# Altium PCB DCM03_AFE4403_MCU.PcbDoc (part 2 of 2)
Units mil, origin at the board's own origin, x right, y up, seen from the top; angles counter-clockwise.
Board outline 608.6 x 413.33 mil, 6 copper layers (Top Layer, Mid-Layer 1, Mid-Layer 2, Mid-Layer 3, Mid-Layer 4, Bottom Layer); 22 components, 39 nets, 207 pads, 99 vias.
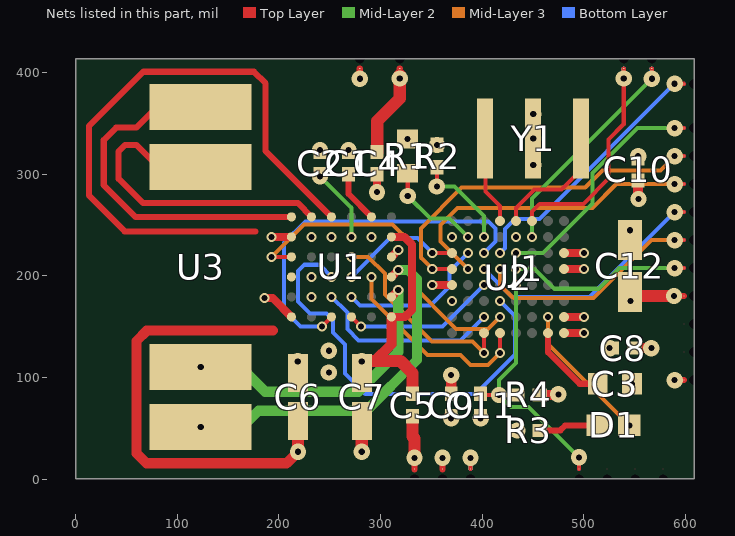
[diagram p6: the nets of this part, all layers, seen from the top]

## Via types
v1: diameter 16, hole 6, Top Layer to Bottom Layer, 50 vias
v2: diameter 10, hole 6, Top Layer to Bottom Layer, 49 vias

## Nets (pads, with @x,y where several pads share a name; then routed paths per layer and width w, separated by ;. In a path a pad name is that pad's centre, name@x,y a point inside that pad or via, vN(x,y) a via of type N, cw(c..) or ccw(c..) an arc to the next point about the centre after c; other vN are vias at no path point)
AFE_ADC_RDY: U1.D5 U2.F7 | length 187.1
  Bottom Layer w4: v2(251.76,179.42) 267.35,163.83 267.35,147.62 278.49,136.48 378.88,136.48 v2(401.98,159.58)
AFE_DIAG_END: U1.B4 U2.E8 | length 199.8
  Top Layer w4: v2(417.73,124.33) U2.E8@417.73,143.83
  Mid-Layer 3 w4: v2(291.13,199.1) 291.13,177.29 346.41,122.01 378.87,122.01 388.57,112.31 405.71,112.31 v2(417.73,124.33)
AFE_PDNZ: U1.C3 U2.F8 | length 201.1
  Top Layer w4: v2(401.98,124.33) U2.F8@401.98,143.83
  Mid-Layer 3 w4: v2(271.44,218.79) 287.84,218.79 304.36,202.27 304.36,181.9 350.56,135.7 390.61,135.7 v2(401.98,124.33)
AFE_RESETZ: U1.D4 U2.E6 | length 420
  Bottom Layer w4: v2(251.76,199.1) 239.82,211.05 225.32,211.05 219.02,204.75 219.02,174.78 230.86,162.94 246.74,162.94 253.32,156.36 253.32,144.45 265.08,132.69 265.08,103.79 285.05,83.82 393.61,83.82 432.28,122.49 432.28,160.77 v2(417.73,175.32)
AFE_SPI_CLK: U1.C6 U2.F5 | length 151.4
  Top Layer w4: U1.C6@271.44,159.73 v2(280.89,150.29)
  Bottom Layer w4: v2@280.89,150.18 360.89,150.18 401.79,191.07 v2(401.98,191.07)
AFE_SPI_SIMO: U1.C4 U2.H3 | length 120.9
  Top Layer w4: v2(350.98,222.57) U2.H3@370.48,222.57
  Bottom Layer w4: v2(271.44,199.1) 309.61,237.27 336.28,237.27 v2(350.98,222.57)
AFE_SPI_SOMI: U1.C5 U2.G3 | length 148.3
  Bottom Layer w4: v2(271.44,179.42) 280,170.87 349.12,170.87 367.89,189.64 367.89,204.23 v2(386.23,222.57)
AFE_SPI_STE: U1.D6 U2.F3 | length 372.5
  Top Layer w4: v2(242.31,150.29) U1.D6@251.76,159.73
  Bottom Layer w4: v2(242.31,150.29) 221.08,150.29 204.94,166.43 204.94,232.72 226.01,253.79 406.27,253.79 413.2,246.86 413.2,233.79 v2(401.98,222.57)
AFE_VCC: C4.1 J1.1 U1.E4 U1.E5 U1.F2 | length 120.8
  Top Layer w6: v1@318.93,397.7 318.93,404.07 J1.1@318.97,404.11
  Top Layer w8: v2(192.88,238.47) U1.F2@212.39,238.47
  Top Layer w12: C4.1@296.6,321.97 296.81,322.18 296.81,352.64 318.93,374.76 v1@318.93,397.7
  Bottom Layer w4: v1(318.97,394.26) J1.1@318.97,404.11
  other v2: 232.07,179.42 232.07,199.1
AFE_XIN: U1.F3 U2.E7 | length 328.6
  Top Layer w4: v2(192.88,218.79) U1.F3@212.39,218.79
  Mid-Layer 3 w4: v2(192.88,218.79) 224.75,250.66 312.01,250.66 329.38,233.29 329.38,192.99 374.52,147.85 406,147.85 v2(417.73,159.58)
AFE_XOUT: U1.F4
BG: C2.1 U1.C2 | length 72.3
  Mid-Layer 2 w4: v1(240.6,297.95) 271.44,267.11 v2(271.44,238.47)
DVCC: C8.1 C9.1 C10.1 C12.1 J1.21 R4.2 U2.A3 U2.A7 U2.H5 | length 196.8
  Top Layer w6: v1(588.9,180.35) J1.21@598.75,180.35
  Top Layer w8: v2(350.98,191.07) U2.H5@370.48,191.07 ; U2.A7@480.72,159.58 v2(500.22,159.58) ; U2.A3@480.72,222.57 v2(500.22,222.57)
  Top Layer w10: v1@369.15,100.84 v1@369.6,100.39 ; v1(369.6,102.39) v1@369.6,100.39 ; C9.1@370.09,84.46 C9.1@369.6,83.97 v1@369.6,100.39 ; R4.2@456.62,82.95 474.55,82.95 v1(475.06,83.46) ; C8.1@549.62,128.95 v1(566.63,128.95) ; C10.1@553.6,293.92 553.6,276.04 v1(554.01,275.63)
  Top Layer w12: v1(546.17,175.52) 551,180.35 v1(588.9,180.35)
  Bottom Layer w4: v1(588.9,180.35) J1.21@598.75,180.35
EXT_SPI_CLK: J1.9 U2.F4 | length 252.3
  Top Layer w4: v1(589.56,262.8) 598.52,262.8 J1.9@598.75,263.03
  Bottom Layer w4: v2(401.98,206.82) 429.69,179.11 505.87,179.11 v1(589.56,262.8) 589.79,263.03 J1.9@598.75,263.03
EXT_SPI_SIMO: J1.8 U2.H4 | length 361.9
  Top Layer w4: v2(350.98,206.82) U2.H4@370.48,206.82 ; v1(589.56,317.92) 598.52,317.92 J1.8@598.75,318.14
  Mid-Layer 3 w4: v2(350.98,206.82) 339.85,217.95 339.85,246.9 379.86,286.91 501.56,286.91 518.43,303.78 575.42,303.78 v1(589.56,317.92)
  Bottom Layer w4: v1(589.56,317.92) 589.79,318.14 J1.8@598.75,318.14
EXT_SPI_SOMI: J1.7 U2.G4 | length 320.2
  Top Layer w4: v1(589.56,290.36) 598.52,290.36 J1.7@598.75,290.58
  Mid-Layer 3 w4: v2(386.23,206.82) 359.19,233.86 359.19,250.32 375.87,267 508.7,267 532.06,290.36 v1(589.56,290.36)
  Bottom Layer w4: v1(589.56,290.36) 589.79,290.58 J1.7@598.75,290.58
EXT_SPI_STE: J1.6 U2.E4 | length 235.4
  Top Layer w4: v1(589.56,235.24) 598.52,235.24 J1.6@598.75,235.47
  Mid-Layer 3 w4: v2@417.73,207.07 v2(417.73,206.82) 417.73,191.08 430.7,178.11 509.64,178.11 566.77,235.24 v1(589.56,235.24)
  Bottom Layer w4: v1(589.56,235.24) 589.79,235.47 J1.6@598.75,235.47
GND: C1.2 C2.2 C3.2 C4.2 C8.2 C9.2 C10.2 C11.2 C12.2 J1.2 J1.10 J1.22 R1.1 R2.2 R3.1 U1.B2 U1.D2 U1.E2 U1.F6 U2.A4 U2.A8 U2.D2 U2.H2 U2.H6 Y1.2 | length 152.8
  Top Layer w4: v1(388.6,20.95) 388.72,20.83 J1.22@388.72,9.8
  Top Layer w6: v1@279.6,394.26 J1.2@279.6,404.11 ; v1(589.56,97.44) 598.52,97.44 J1.10@598.75,97.67
  Top Layer w8: v2(185.9,178.17) 193.96,178.17 U1.F6@212.39,159.73 ; C4.2@296.6,299.92 v1(296.6,282.45) v1@297.57,281.48 ; U2.A8@480.72,143.83 v2(500.22,143.83) ; U2.A4@480.72,206.82 v2(500.22,206.82)
  Bottom Layer w4: J1.2@279.6,404.11 279.6,394.25 v1(279.72,394.14) ; v1(388.6,20.95) 388.72,20.83 J1.22@388.72,9.8 ; v1(589.56,97.44) 589.79,97.67 J1.10@598.75,97.67
  other v1: 434.58,47.95 369.6,59.95 398.6,59.95 547.7,93.49 525.61,128.95 545.6,244.95 450.37,309.23 553.6,317.94 240.6,323.94 268.6,323.94 355.6,328.97 326.6,334.88 450.37,335.23 450.37,359.23
  other v2: 370.48,175.32 232.07,238.47 251.76,238.47 291.13,238.47 370.48,238.32 433.47,238.32
INN: U1.F1 U3.4 | length 351
  Top Layer w6: U3.4@123.07,366.46 80.12,366.46 59.6,345.95 39.86,345.95 27.67,333.76 27.67,289.35 58.86,258.16 U1.F1@212.39,258.16
INP: U1.E1 U3.3 | length 324.7
  Top Layer w6: U3.3@123.07,307.41 81.14,307.41 59.6,328.95 48.66,328.95 42.35,322.64 42.35,295.67 66.33,271.69 218.86,271.69 232.07,258.47 U1.E1@232.07,258.16
JTAG_RST: C11.1 J1.17 R4.1 U2.D5 | length 279.1
  Top Layer w4: C11.1@398.6,83.97 399.62,82.95 R4.1@434.58,82.95 ; J1.17@495.3,9.8 v1(495.3,21.5)
  Mid-Layer 2 w4: v2(433.47,191.07) 433.47,114.22 416.76,97.51 v1(416.76,82.78) 428.32,71.22 445.57,71.22 v1(495.3,21.5)
  Bottom Layer w4: v1(495.3,21.5) 495.6,21.2 J1.17@495.6,9.8
JTAG_TCK: J1.19 U2.C2 | length 224.7
  Top Layer w4: J1.19@567,404.11 567.12,403.99 v1(567.12,394.14)
  Mid-Layer 2 w4: v2(449.22,238.32) 449.22,276.24 v1(567.12,394.14)
  Bottom Layer w4: J1.19@567,404.11 567,394.25 v1(567.12,394.14)
JTAG_TDI: J1.18 U2.D4 | length 191.1
  Top Layer w4: v1(589.56,207.68) 598.52,207.68 J1.18@598.75,207.91
  Mid-Layer 2 w4: v2(433.47,206.82) 451.79,206.82 471.21,187.4 514.76,187.4 535.04,207.68 v1(589.56,207.68)
  Bottom Layer w4: v1(589.56,207.68) 589.79,207.91 J1.18@598.75,207.91
JTAG_TDO: J1.15 U2.D3 | length 243.2
  Top Layer w4: v1(589.56,345.47) 598.52,345.47 J1.15@598.75,345.7
  Mid-Layer 2 w4: v2(433.47,222.57) 460.07,222.57 508.62,271.12 508.62,301.21 553.01,345.59 v1@589.56,345.59
  Bottom Layer w4: v1(589.56,345.47) 589.79,345.7 J1.15@598.75,345.7
JTAG_TEST: J1.20 U2.E3 | length 270.5
  Top Layer w4: v1(589.56,389.2) 598.61,389.2 J1.20@598.75,389.06
  Bottom Layer w4: v2(417.73,222.57) 422.44,227.28 422.44,246.37 432.23,256.16 456.52,256.16 v1(589.56,389.2) 589.7,389.06 J1.20@598.75,389.06
JTAG_TMS: J1.16 U2.C1 | length 222.4
  Top Layer w4: U2.C1@449.22,254.07 449.22,263.46 456.75,270.99 499.65,270.99 524.37,295.71 524.37,334.26 539.44,349.33 J1.16@539.44,404.11
  Bottom Layer w4: v1(539.44,394.26) J1.16@539.44,404.11
LED1: D1.A U2.B7 | length 139.8
  Mid-Layer 3 w4: v2(464.97,159.58) 464.97,132.93 v1(544.95,52.95)
LED_DRV_GND: C5.2 C6.2 C7.2 J1.13 U1.A3 | length 562.5
  Top Layer w6: J1.13@333.6,9.8 v1@333.6,20.83
  Top Layer w8: U1.A3@310.81,218.79 v2(317.46,225.44)
  Top Layer w10: 194.28,146.2 70.02,146.2 59.87,136.05 59.87,25.39 69.64,15.62 207.6,15.62 v1(218.93,26.95)
  Top Layer w12: C6.2@218.6,57.33 218.93,57 v1(218.93,26.95) ; v1(281.6,26.95) C7.2@281.6,57.33 ; C5.2@331.6,61.92 331.6,41.99 333.6,39.99 v1(333.6,20.95)
  Bottom Layer w4: J1.13@333.6,9.8 v1(333.6,20.95) J1.13@333.6,9.8
LED_DRV_SUP: C5.1 C6.1 C7.1 J1.14 U1.A2 U1.A6 | length 271.4
  Top Layer w6: J1.14@361.16,9.8 v1@361.16,20.83
  Top Layer w8: U1.A6@310.81,159.73 324.23,159.73 331.14,166.65 331.14,230.89 323.55,238.47 U1.A2@310.81,238.47
  Top Layer w10: v1(281.6,115.95) 294.03,115.95 310.81,132.73 U1.A6@310.81,159.73
  Top Layer w12: 292.83,116.28 319.59,116.28 331.6,104.27 C5.1@331.6,83.97
  Bottom Layer w4: v1(361.04,20.95) v1@361.16,20.83 ; v1@361.16,20.83 J1.14@361.16,9.8 v1@361.16,20.83
  other v1: 249.22,104.96 218.6,115.95 249.22,126.43
NetC3_1: C3.1 U2.B8 | length 80.5
  Top Layer w6: U2.B8@464.97,143.83 464.97,124.9 495.92,93.95 C3.1@513.67,93.95
NetD1_K: D1.K R3.2 | length 59.6
  Top Layer w6: R3.2@456.62,47.95 477,47.95 481.86,52.81 D1.K@514.25,52.81
NetR2_1: R2.1 U2.F2 | length 97.2
  Top Layer w4: v1@355.5,289.02 355.6,289.12 R2.1@355.6,306.92
  Mid-Layer 2 w4: v1(355.5,288.02) 373,288.02 401.98,259.04 v2(401.98,238.32)
PUR: R1.2 U2.G2 | length 98.6
  Top Layer w4: v1@326.76,278.55 v1(326.86,278.65) R1.2@326.86,301.02
  Mid-Layer 2 w4: v1(326.86,278.65) 349.03,256.48 368.07,256.48 v2(386.23,238.32)
TX_REF: C1.1 U1.B1 | length 49.1
  Top Layer w6: C1.1@268.6,297.95 268.6,280.69 U1.B1@291.13,258.16
TXN: U1.A4 U3.1 | length 351.5
  Top Layer w8: U1.A4@310.81,199.1 v2(317.46,205.75)
  Mid-Layer 2 w10: v1(123.07,51.26) 163.91,51.26 179.94,67.29 286.05,67.29 336.01,117.25 336.01,196.98 327.1,205.89 v2@317.6,205.89
TXP: U1.A5 U3.2 | length 290.9
  Top Layer w8: U1.A5@310.81,179.42 v2(317.46,186.07)
  Mid-Layer 2 w10: v1(123.07,110.56) 161.99,110.56 186.46,86.09 278.21,86.09 317.46,125.34 v2(317.46,186.07)
VCM: U1.D1 | length 605.6
  Top Layer w6: 176.81,243.95 48.27,243.95 13,279.22 13,347.35 66.6,400.95 175.49,400.95 186.96,389.48 186.96,322.96 U1.D1@251.76,258.16
XT2IN: U2.E1 Y1.1 | length 87.1
  Top Layer w4: Y1.1@403.36,335.23 403.36,283.19 417.73,268.82 U2.E1@417.73,254.07
XT2OUT: U2.D1 Y1.3 | length 123.3
  Top Layer w4: U2.D1@433.47,254.07 433.47,266.82 451.7,285.05 478.16,285.05 497.84,304.73 Y1.3@497.84,335.23
pads on no net: J1.0 J1.3 J1.4 J1.5 J1.11 J1.12 U1.A1 U1.B3 U1.B5 U1.B6 U1.C1 U1.D3 U1.E3 U1.E6 U1.F5 U2.A1 U2.A2 U2.A5 U2.A6 U2.B1 U2.B2 U2.B3 U2.B4 U2.B5 U2.B6 U2.C3 U2.C4 U2.C5 U2.C6 U2.C7 U2.C8 U2.D6 U2.D7 U2.D8 U2.E2 U2.E5 U2.F1 U2.F6 U2.G1 U2.G5 U2.G6 U2.G7 U2.G8 U2.H1 U2.H7 U2.H8

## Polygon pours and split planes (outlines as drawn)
AFE_VCC on Mid-Layer 4 "MidLayer1-No Net" (solid, remove dead copper, pour order 14): 337.4,403.77 337.4,260.88 328.02,251.5 305.31,251.5 297.38,243.57 297.38,153.44 289.81,145.87 219.11,145.87 194.84,170.14 11.58,170.14 11.58,403.84
LED_DRV_SUP on Mid-Layer 4 "Top Layer-No Net" (solid, remove dead copper, pour order 18): 9.91,154.63 195.24,154.61 211.95,137.88 298.43,137.9 306.31,145.72 306.31,199.62 306.27,240.58 308.83,243.13 324.82,243.17 335.13,232.86 335.13,68.36 369.33,34.49 369.29,11.35 9.98,12.14
DVCC on Mid-Layer 4 "Top Layer-No Net" (solid, remove dead copper, pour order 15): 416.96,10.95 342.65,85.26 342.65,380.7 365.32,403.37 598.22,403.37 598.22,10.95
LED_DRV_GND on Mid-Layer 1 "Top Layer-No Net" (solid, remove dead copper, pour order 17): 9.91,154.52 195.24,154.59 211.95,137.86 298.43,137.88 306.31,145.7 306.31,199.6 306.27,240.56 308.83,243.11 324.82,243.15 337.88,230.09 337.88,65.62 366.38,37.39 366.33,11.98 274.82,11.07 184.01,10.9 9.98,10.63
GND on Mid-Layer 1 "Bottom Layer-No Net 1" (solid, remove dead copper, pour order 26): 10,402.34 10.01,174.58 13.78,170.81 196.74,170.81 196.74,170.76 218.88,148.62 291.1,148.62 298.43,155.95 298.43,245.49 306.85,253.91 330.55,253.91 330.55,253.43 350,233.98 350,69.94 380.17,39.77 380.17,17.01 385.46,11.71 598.08,11.71 598.06,402.34
LED_DRV_SUP on Top Layer "Top Layer-No Net" (solid, remove dead copper, pour order 10): 195.95,97.8 192,101.75 192,124.35 205.51,137.86 332.98,137.86 337.88,132.96 337.88,100.51 335.17,97.8
LED_DRV_GND on Mid-Layer 2 "Top Layer-No Net" (solid, remove dead copper, pour order 16): 10.54,153.67 196.95,153.74 213.66,137.01 300.14,137.03 308.02,144.85 308.02,198.75 307.98,239.71 310.54,242.26 326.53,242.3 339.59,229.24 339.59,60.09 371.03,28.95 371,11.74 10.6,12.5
GND on Mid-Layer 2 "MidLayer1-No Net" (solid, remove dead copper, pour order 12): 10.35,170.86 195.87,170.81 218,148.62 291.36,148.81 297.52,154.95 297.52,245.49 305.94,253.91 329.63,253.91 351.62,231.91 351.62,65.63 379.06,37.99 379.22,11.04 598.19,11.04 598.19,402.37 10.3,402.37
no net on Drill Drawing (solid): 23534.26,-12571.01 23558.9,-12458.76 23530.63,-12458.94 23505.62,-12571.01 23534.26,-12571.01
no net on Drill Drawing (solid): 23564.3,-12419.41 ccw(c23550.34,-12419.41) 23550.34,-12405.45 ccw(c23550.34,-12419.41) 23536.38,-12419.41 ccw(c23550.34,-12419.41) 23550.34,-12433.37 ccw(c23550.34,-12419.41) 23564.3,-12419.41
no net on Drill Drawing (solid): 23473.3,-12427.63 23476.67,-12433.2 23482.5,-12437.43 23484.9,-12439.39 23496.56,-12442 23503.42,-12443.95 23522.33,-12444.97 23514.96,-12476.28 23485.46,-12476.28 23475.5,-12519.01 23506.16,-12519.38 23494.65,-12570.85 23495.19,-12579.31 23496.91,-12586.48 23498.62,-12592.03 23503.42,-12597.9 23511.31,-12603.44 23521.6,-12606.05 23533.95,-12607.03 23544.93,-12604.42 23555.91,-12600.18 23561.1,-12584.65 23553.5,-12582.9 23548.36,-12579.31 23545.61,-12576.7 23545.96,-12572.14 23545.96,-12567.9 23557.47,-12519.59 23587.88,-12519.59 23597.71,-12476.05 23567.82,-12476.05 23566.53,-12474.7 23571.45,-12448.38 23616.7,-12448.26 23623.07,-12450.51 23630.27,-12453.12 23640.22,-12454.75 23650.85,-12456.71 23659.77,-12457.36 23659.09,-12481.49 23659.77,-12488.66 23659.77,-12493.55 23661.83,-12500.73 23663.89,-12506.27 23666.63,-12509.53 23669.03,-12514.42 23669.72,-12518.66 23670.41,-12522.25 23670.41,-12556.49 23670.75,-12568.22 23668.35,-12580.29 23652.57,-12586.81 23628.9,-12598.55 23612.44,-12608.66 23594.6,-12623.66 23589.45,-12628.87 23582.59,-12638.33 23577.79,-12646.94 23575.39,-12651.5 23570.93,-12661.61 23568.87,-12665.2 23566.13,-12681.18 23566.13,-12735.63 23556.18,-12735.96 23550.35,-12734.65 23540.74,-12732.7 23532.17,-12729.11 23520.51,-12723.57 23510.9,-12717.04 23496.49,-12705.96 23487.58,-12693.24 23478.66,-12678.24 23472.14,-12658.02 23466.65,-12640.42 23458.42,-12621.83 23446.76,-12603.24 23442.64,-12598.03 23436.81,-12594.8 23425.15,-12590.89 23407.99,-12590.24 23401.82,-12591.87 23395.1,-12600.34 23387.55,-12609.15 23377.94,-12611.43 23362.51,-12596.76 23354.96,-12584.69 23349.13,-12570.34 23340.56,-12558.93 23328.55,-12548.5 23315.51,-12535.62 23304.54,-12519.32 23300.42,-12510.51 23297.68,-12497.14 23396.21,-12497.36 23396.21,-12367.86 23473.18,-12367.91 23473.3,-12427.63
GND on Mid-Layer 3 "MidLayer1-No Net" (solid, remove dead copper, pour order 11): 9.79,169.84 195.71,169.78 217.85,147.59 291.24,147.78 297.4,153.92 297.4,244.46 305.82,252.88 329.52,252.88 351.52,230.88 351.52,66.55 378.96,38.92 379.11,11.5 598.03,11.5 598.03,403.53 9.98,403.53

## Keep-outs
Keep-Out Layer:
  lines w1: 0,413.95 0,0 608.59,0 608.59,414.05 0,414.05
  text ".Layer_Name" at 517.95,-905.04 h60

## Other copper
Top Layer:
  text "TOP SIDE" at -16,-1144 h75
  text "1" at 358,-1263 h75
Mid-Layer 1:
  text "GND SPLIT PLANE 1" at -16,-1143 h75
  text "2" at 359,-1263 h75
Mid-Layer 2:
  text "SIGNAL 1" at -15.01,-1143.38 h75
  text "3" at 360,-1263 h75
Mid-Layer 3:
  text "SIGNAL 2" at -13,-1143 h75
  text "4" at 360,-1263 h75
Mid-Layer 4:
  text "POWER SPLIT PLANE 1" at -16,-1143 h75
  text "5" at 360,-1263 h75
Bottom Layer:
  text "BOTTOM SIDE" at -17,-1144 h75
  text "6" at 360,-1263 h75

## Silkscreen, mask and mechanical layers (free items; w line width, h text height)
Top Overlay:
  lines w6: 192.5,126.5 203.5,126.5 ; 198,121 198,132 ; 296.5,126 307.5,126 ; 302,120.5 302,131.5 ; 564.5,160 575.5,160 ; 570,154.5 570,165.5
  text "TOP SILKSCREEN" at -16,-1145 h75
  text "11" at 320,-1262 h75
Bottom Overlay:
  text "DCM03_AFE4403" at 413,349 h30
  text "_MCU" at 144,303 h30
  text "REV X0" at 204,252 h30
  text "BOTTOM SILKSCREEN" at -16,-1146 h75
  text "12" at 320,-1262 h75
Top Paste:
  drawing of 22 lines, arcs and shapes, not listed
  text "TOP PASTE" at -16,-1144 h75
  text "9" at 360,-1263 h75
Bottom Paste:
  drawing of 24 lines, arcs and shapes, not listed
  text "BOTTOM PASTE" at -14,-1145 h75
  text "10" at 316,-1263 h75
Top Solder:
  text "TOP SOLDERMASK" at -16,-1144 h75
  text "7" at 360,-1263 h75
Bottom Solder:
  text "BOTTOM SOLDERMASK" at -17,-1142 h75
  text "8" at 360,-1263 h75
Drill Guide:
  text ".Layer_Name" at 517.95,-905.04 h60
M1 Board Outline:
  drawing of 409 lines, arcs and shapes, not listed
  text "TEXAS INSTRUMENTS INC." at -39.03,-534.25 h80
  text "2013" at 120.97,-700.25 h80
  text "DCM03_AFE4403_MCU" at -15,-881 h75
  text "PCB REV X0" at -15.03,-1022.25 h75
  text "SHEET   OF 13" at -22.03,-1263.25 h75
  text "25-NOV-2013" at -13.03,-1396.25 h75
M2 Board Dimensions:
  rectangle: 65.45,-457.05 440.45,-332.05
  rectangle: -59.55,-332.05 65.45,-207.05
  lines w7: -59.55,-332.05 940.45,-332.05 ; 65.45,-457.05 65.45,-207.05 ; 190.45,-457.05 190.45,-207.05 ; 440.45,-457.05 440.45,-207.05 ; 690.45,-457.05 690.45,-207.05 ; -59.55,-457.05 -59.55,-207.05 940.45,-207.05 940.45,-457.05 -59.55,-457.05
  lines w10: -59.55,-522.05 -59.55,-502.05 ; 0.45,-532.05 -59.55,-512.05 ; 0.45,-492.05 -59.55,-512.05 ; 164.53,-512.05 -59.55,-512.05 ; 716.36,-512.05 940.45,-512.05 ; 880.45,-532.05 940.45,-512.05 ; 880.45,-492.05 940.45,-512.05 ; 940.45,-522.05 940.45,-502.05
  text "1000 (mil)" at 174.53,-548.04 h60
  text ".Layer_Name" at 517.95,-905.04 h60
M3 3D STEP Top:
  text ".Layer_Name" at 517.95,-905.04 h60
M4 3D STEP Bottom:
  text ".Layer_Name" at 517.95,-905.04 h60
M6 Assembly Bottom:
  lines w10: -351.55,-773.88 6250.45,-773.88 ; -349.55,-977.22 6250.45,-977.22 ; 1056.45,-1187.05 1056.45,-984.22 ; 1678.45,-773.88 1678.45,-570.55 ; 2518.45,-773.88 2518.45,-570.55 ; 3785.45,-1180.55 3785.45,-570.55 ; 4674.45,-1180.55 6249.95,-1180.55 6249.95,-570.55 -351.55,-570.55 -351.55,-1180.55 2245.45,-1180.55 6250.45,-1180.55 6250.45,-570.55
  text "COMPONENTS MARKED 'DNP' SHOULD NOT BE POPULATED." at 6042.95,-364.55 h60
  text ".VariantName" at 4998.95,-480.55 h60
  text "ASSEMBLY VARIANT:" at 6037.95,-480.55 h60
  text ".VersionControl_RevNumber" at 976.45,-702.72 h60
  text "SVN REV:" at 1482.45,-702.72 h60
  text ".PCB_Rev" at 2028.95,-702.72 h60
  text "REV:" at 2320.45,-702.72 h60
  text ".PRJ_Number" at 3164.95,-702.72 h60
  text "BOARD #:" at 3710.45,-702.72 h60
  text "PCB VIEWED FROM BOTTOM SIDE" at 6186.95,-702.72 h60
  text "IGNORE ->" at 2488.8,-905.04 h60
  text "TEXAS INSTRUMENTS" at 845.45,-1111.38 h60
  text ".Print_Time" at 2109.95,-1111.38 h60
  text ".Print_Date" at 2838.95,-1111.38 h60
  text "GENERATED    :" at 3708.45,-1111.38 h60
  text ".plot_File_Name" at 5381.45,-1111.38 h60
  text "PLOT NAME =" at 6186.95,-1111.38 h60
M7 LPKF Text Top:
  drawing of 57 lines, arcs and shapes, not listed
  text "1" at -3381.03,5868.19 h70
  text "2" at -885.36,5868.19 h70
  text "3" at 1603.98,5868.19 h70
  text "4" at 4110.65,5868.19 h70
  text "5" at 6609.64,5868.19 h70
  text "6" at 9114.64,5868.19 h70
  text "A" at -4537.36,4725.19 h70
  text "A" at 10262.64,4725.19 h70
  text "B" at -4537.36,2345.19 h70
  text "B" at 10262.64,2345.19 h70
  text "C" at -4537.36,-29.81 h70
  text "C" at 10262.64,-29.81 h70
  text "PROJECT TITLE:" at 7222.64,-1890.81 h45
  text ".PRJ_Title" at 7272.64,-2024.14 h70
  text "DESIGNED FOR:" at 7222.64,-2191.81 h45
  text ".PRJ_Customer" at 7272.64,-2331.81 h70
  text "D" at -4537.36,-2399.81 h70
  text "D" at 10262.64,-2399.81 h70
  text "FILE NAME:" at 7222.64,-2491.81 h45
  text ".PCB_File_Name_No_Path" at 7272.64,-2611.81 h70
  text "Texas Instruments (TI) and/or its licensors do not warrant the accuracy or completeness of this specification" at 2253.14,-2773.65 h45
  text "ENGINEER:" at 7222.64,-2781.81 h45
  text "LAYOUT BY:" at 8727.64,-2781.81 h45
  text "or any information contained therein. TI and/or its licensors do not warrant that this design will meet" at 2208.15,-2886.31 h45
  text ".PRJ_Engineer" at 7272.64,-2936.8 h70
  text ".PCB_Layout" at 8778.14,-2936.8 h70
  text "the specifications, will be suitable for your application or fit for any particular purpose, or will operate in" at 2208.15,-2998.98 h45
  text ".Layer_Name" at -3543.86,-3026.8 h60
  text "ALTIUM DESIGNER VERSION:" at 8727.64,-3091.81 h45
  text "an implementation. TI and/or its licensors do not warrant that the design is production worthy. You should" at 2208.15,-3111.64 h45
  text "completely validate and test your design implementation to confirm the system functionality for your application." at 2253.14,-3224.31 h45
  text ".print_Scale" at 7272.64,-3225.14 h70
  text ".Application_BuildNumber" at 8778.14,-3225.14 h70
  text "1" at -3381.03,-3431.81 h70
  text "2" at -885.36,-3431.81 h70
  text "3" at 1603.98,-3431.81 h70
  text "4" at 4110.65,-3431.81 h70
  text "5" at 6609.64,-3431.81 h70
  text "6" at 9114.64,-3431.81 h70
M8 LPKF Text Bottom:
  drawing of 212 lines, arcs and shapes, not listed
  text "DESIGN INFORMATION" at 8260.15,4641.69 h60
  text "(REFER ALSO ARRAY/PANEL PROFILING INFORMATION)" at 7898.6,4479.98 h60
  text "BOARD SIZE" at 7212.6,4475.69 h60
  text "3450MIL" at 7674.92,4347.87 h60
  text "X" at 8180.6,4347.87 h60
  text "4950MIL" at 8411.92,4347.87 h60
  text "Number of Layers :" at 7615.6,4150.69 h60
  text "2" at 8710.41,4140.69 h60
  text "MIN. TRACK WIDTH:" at 7615.6,4011.69 h60
  text "8" at 8711.84,4011.69 h60
  text "MIL" at 8866.6,4011.69 h60
  text "MIN. CLEARANCE:" at 7615.6,3879.69 h60
  text "8" at 8711.84,3879.69 h60
  text "MIL" at 8866.6,3879.69 h60
  text "MIN. VIA PAD SIZE:" at 7615.6,3747.69 h60
  text "24" at 8681.85,3747.69 h60
  text "MIL" at 8866.6,3747.69 h60
  text "0.05mm (2MIL)" at 8310.6,3605.98 h60
  text "MINIMUM ANNULAR RING" at 7286.36,3601.7 h60
  text "EXTERNAL" at 9018.6,3601.7 h60
  text "PER" at 7486.36,3483.69 h60
  text "IPC-D-275 CLASS 2 LEVEL C" at 7706.36,3483.69 h60
  text "MIL, HOLES" at 9194.6,3371.4 h60
  text "+/-" at 8802.14,3370.69 h60
  text "+/-" at 9656.14,3370.69 h60
  text "REGISTRATION TOLERANCES:" at 7286.36,3365.69 h60
  text "METAL" at 8486.14,3365.69 h60
  text "5" at 9062.34,3365.69 h60
  text "3" at 9895.34,3365.69 h60
  text "MIL" at 10011.6,3365.69 h60
  text "MATERIAL:" at 7211.6,3156.23 h60
  text "FR-4 High Tg" at 8198.04,3015.9 h60
  text "FR-408" at 7632.6,3007.33 h60
  text "X" at 8044.6,3007.33 h60
  text "OTHER" at 9120.6,3007.33 h60
  text "62 MIL (1.6mm) +/-10%" at 7952.7,2844.61 h60
  text "THICKNESS:" at 7286.36,2840.33 h60
  text "X" at 7824.53,2840.33 h60
  text "OTHER" at 9237.6,2840.33 h60
  text "TOLERANCE:" at 7286.36,2682.33 h60
  text "X" at 8125.67,2682.33 h60
  text "ANSI IPC-6012 TYPE 3 CLASS 2" at 8312.61,2682.33 h60
  text "OTHER +/-" at 8312.6,2526.33 h60
  text "BOW & TWIST:" at 7286.36,2369.33 h60
  text "X" at 8125.67,2369.33 h60
  text "ANSI IPC-6012 TYPE 3 CLASS 2" at 8312.61,2369.33 h60
  text "OTHER +/-" at 8312.6,2210.82 h60
  text "COPPER THICKNESS (FINISHED):" at 7211.6,2075.33 h60
  text "1.4MIL (1oz)" at 8091.6,1922.61 h60
  text "2MIL (1.4oz)" at 8858.6,1922.61 h60
  text "2.8MIL (2oz)" at 9585.6,1922.61 h60
  text "OUTER:" at 7568.6,1918.33 h60
  text "X" at 7963.14,1917.69 h60
  text "1.4MIL (1oz)" at 8091.6,1765.61 h60
  text "2.8MIL (2oz)" at 8858.6,1765.61 h60
  text "N/A" at 9585.14,1765.98 h60
  text "INNER SIGNAL:" at 7279.52,1761.33 h60
  text "X" at 7964.56,1761.33 h60
  text "DRILLING:" at 7211.6,1622.33 h60
  text "REFERENCE:" at 7286.36,1505.33 h60
  text "X" at 7934.6,1505.33 h60
  text "AS SHOWN" at 8121.6,1505.33 h60
  text "X" at 8835.6,1505.33 h60
  text "NC_DRILL FILES" at 8972.6,1505.33 h60
  text "PTH MIN COPPER THICKNESS:" at 7286.36,1347.33 h60
  text "X" at 8636.6,1347.33 h60
  text "1MIL" at 8773.6,1347.33 h60
  text "OTHER" at 9270.6,1347.33 h60
  text "BOARD FINISH:" at 7211.6,1188.33 h60
  text "SILKSCREEN:" at 7366.82,1070.33 h60
  text "X" at 8315.6,1070.33 h60
  text "TOP" at 8441.6,1070.33 h60
  text "X" at 8825.6,1070.33 h60
  text "BOTTOM" at 8952.6,1070.33 h60
  text "SILKSCREEN COLOR:" at 7366.82,903.33 h60
  text "X" at 8314.56,903.33 h60
  text "WHITE" at 8441.6,903.33 h60
  text "OTHER" at 8952.6,903.33 h60
  text "SOLDER RESIST COLOR:" at 7366.82,733.33 h60
  text "X" at 7934.56,574.13 h60
  text "GREEN" at 8061.6,574.13 h60
  text "BLUE" at 8652.6,574.13 h60
  text "OTHER" at 9190.6,574.13 h60
  text "IMMERSION GOLD (ENIG)" at 8272.6,385.61 h60
  text "ENEPIG" at 9610.14,382.33 h60
  text "SURFACE FINISH:" at 7211.6,381.33 h60
  text "X" at 8085.65,381.33 h60
  text "IMM. TIN/SILVER OR EQUIV" at 7541.14,224.33 h60
  text "OTHER" at 8972.6,224.33 h60
  text "ARRAY/PANEL:" at 7211.6,45.33 h60
  text "CUT AND TRIM PER MECH LAYER 1" at 8272.6,41.04 h60
  text "N.C. ROUTE" at 8272.6,-110.67 h60
  text "X" at 8951.6,-110.67 h60
  text "V. SCORE" at 9138.6,-110.67 h60
  text "CERTIFICATION:" at 7211.6,-247.67 h60
  text "MATERIALS AND WORKMANSHIP FOR ALL PCBS" at 7936.6,-247.67 h60
  text "TO MEET OR EXCEED THE REQUIREMENTS OF:" at 7936.6,-345.67 h60
  text "X" at 7563.1,-482.17 h60
  text "ANSI IPC-A-600F CLASS ->" at 7702.1,-482.17 h60
  text "X" at 9341.15,-482.17 h60
  text "2" at 9460.1,-482.17 h60
  text "1" at 9145.1,-483.67 h60
  text "3" at 9814.1,-483.67 h60
  text "X" at 7565.15,-641.67 h60
  text "UL 94V-0" at 7702.1,-641.67 h60
  text "X" at 8377.15,-641.67 h60
  text "RoHS" at 8514.1,-641.67 h60
  text "OTHER" at 9158.5,-641.67 h60
  text "PER ORDER" at 9555.56,-641.67 h60
  text "ADDITIONAL REQUIREMENTS:" at 7211.6,-782.67 h60
  text "MICROSECTION:" at 7286.36,-897.67 h60
  text "YES" at 8192.1,-897.67 h60
  text "REQUIRED" at 9053.6,-1053.81 h60
  text "BARE BOARD ELEC. TEST:" at 7286.36,-1056.67 h60
  text "NONE" at 8592.1,-1056.67 h60
  text "X" at 8926.6,-1056.67 h60
  text "PER ORDER" at 9645.6,-1056.67 h60
  text "MANUFACTURER'S UL:" at 7286.36,-1213.67 h60
  text "RAIL" at 8452.1,-1217.96 h60
  text "METAL" at 8943.91,-1217.96 h60
  text "X" at 9319.14,-1218.31 h60
  text "SILK" at 9455.6,-1217.96 h60
  text ".Layer_Name" at -3543.86,-3026.8 h60
M9 Title Sheet:
  lines w10: -351.05,-976.72 6248.95,-976.72 ; -351.05,-773.38 6250.95,-773.38 ; -351.05,-570.05 -351.05,-1180.05 3653.95,-1180.05 6250.95,-1180.05 6250.95,-570.05 -350.55,-570.05 -350.55,-1180.05 1224.95,-1180.05 ; 2113.95,-1180.05 2113.95,-570.05 ; 3380.95,-773.38 3380.95,-570.05 ; 4220.95,-773.38 4220.95,-570.05 ; 4842.95,-1186.55 4842.95,-983.72
  text "ALL ARTWORK VIEWED FROM TOP SIDE" at -287.55,-702.22 h60
  text "BOARD #:" at 2188.95,-702.22 h60
  text ".PRJ_Number" at 2734.45,-702.22 h60
  text "REV:" at 3578.95,-702.22 h60
  text ".PCB_Rev" at 3870.45,-702.22 h60
  text "SVN REV:" at 4416.95,-702.22 h60
  text ".VersionControl_RevNumber" at 4922.95,-702.22 h60
  text "LAYER NAME =" at -287.55,-905.04 h60
  text "PLOT NAME =" at -287.55,-1110.88 h60
  text ".plot_File_Name" at 517.95,-1110.88 h60
  text "GENERATED    :" at 2190.95,-1110.88 h60
  text ".Print_Date" at 3060.45,-1110.88 h60
  text ".Print_Time" at 3789.45,-1110.88 h60
  text "TEXAS INSTRUMENTS" at 5053.95,-1110.88 h60
M10 Fab Notes:
  lines w6: 7239.14,5291.69 9789.14,5291.69 ; 7239.14,5396.09 9789.14,5396.09 ; 7179.14,4806.69 ccw(c7213.14,4806.69) 7213.14,4772.69 9815.14,4772.69 ccw(c9815.14,4806.69) 9849.14,4806.69 9849.14,5512.69 ccw(c9815.14,5512.69) 9815.14,5546.69 7213.14,5546.69 ccw(c7213.14,5512.69) 7179.14,5512.69 7179.14,4806.69
  text "The Stackup Legend below this is static." at 7484.64,5706.19 h60
  text "If you change the stackup, update the Legend." at 7494.64,5616.19 h60
  text "Layer Stack Up Detail for: Ref_Design.PcbDoc" at 7239.14,5428.79 h57
  text "Layer" at 7239.14,5357.09 h24
  text "Gerber" at 8134.95,5357.09 h24
  text "Copper" at 8698.47,5357.09 h24
  text "Dielectric" at 9301.18,5357.09 h24
  text "Name" at 7239.14,5309.09 h24
  text "Document" at 8134.95,5309.09 h24
  text "Thickness" at 8698.47,5309.09 h24
  text "Material" at 9301.18,5309.09 h24
  text "Top Solder Mask" at 7239.14,5216.13 h34
  text "(.GTS)" at 8134.95,5216.13 h34
  text "Solder Resist" at 9301.18,5216.13 h34
  text "Top Layer" at 7239.14,5119.38 h34
  text "(.GTL)" at 8134.95,5119.38 h34
  text "1.4mil" at 8698.47,5119.38 h34
  text "FR-4" at 9301.18,5071 h34
  text "Bottom Layer" at 7239.14,5022.63 h34
  text "(.GBL)" at 8134.95,5022.63 h34
  text "1.4mil" at 8698.47,5022.63 h34
  text "Bottom Solder Mask" at 7239.14,4925.88 h34
  text "(.GBS)" at 8134.95,4925.88 h34
  text "Solder Resist" at 9301.18,4925.88 h34
  text ".Layer_Name" at -3543.86,-3026.8 h60
Mechanical 13:
  text ".Layer_Name" at 517.95,-905.04 h60
Mechanical 14:
  text ".Layer_Name" at 517.95,-905.04 h60
Mechanical 15:
  text ".Layer_Name" at 517.95,-905.04 h60
Mechanical 16:
  text ".Layer_Name" at 517.95,-905.04 h60
Drill Drawing:
  drawing of 271 lines, arcs and shapes, not listed
  text "8" at -4595,6958 h200
  text "7" at -400,6958 h200
  text "6" at 3855,6958 h200
  text "5" at 8110,6958 h200
  text "4" at 12355,6958 h200
  text "3" at 16600,6958 h200
  text "2" at 20870,6958 h200
  text "1" at 24973.04,6958 h200
  text "SYM" at 22819.5,6719 h94
  text "REVISIONS" at 24520.01,6718.04 h94
  text "X0  ECN DCM03_AFE4403_MCU 11/25/13 MPK" at 22720,6490 h100
  text "D" at 27000,4229.49 h200
  text "GENERAL NOTES: (UNLESS OTHERWISE SPECIFIED)" at 8774,2764 h60
  text "1. FABRICATE PER TI SPECIFICATION 6501320-LATEST REVISION EXCEPT AS NOTED BELOW." at 9024,2564 h60
  text "2. LAMINATE MATERIAL: FR4 ." at 9024,2364 h60
  text "3. COPPER WEIGHT: 0.5 OZ ON ALL LAYERS" at 9024,2164 h60
  text "4. MAXIMUM ALLOWABLE LINE REDUCTION TO BE 20% OR 0.002\" WHICHEVER IS GREATEST." at 9024,1964 h60
  text "5. FINISHED BOARD THICKNESS:  0.020\" +/-10%. SEE DETAIL A." at 9024,1764 h60
  text "6. HOLE POSITION ACCURACY: +/-0.0015\"" at 9024,1564 h60
  text "VIEWED FROM TOP SIDE" at -717.01,1372.62 h156
  text "7. ALL PTH HOLES TO BE PLATED THROUGH 0.001\" MIN COPPER." at 9024,1364 h60
  text "8. BOARD WARP AND TWIST TO BE WITHIN 0.005\" PER LINEAR INCH." at 9024,1164 h60
  text "9. MINIMUM ANNULAR RING OF PLATED-THRU HOLES TO BE 0.002\"" at 9024,964 h60
  text "10. BOARD DIMENSION : 0.609\"X 0.413\"" at 9024,764 h60
  text ".legend" at 3153.45,636.95 h60
  text "11. ALL 0.006\" VIAS NEED TO BE FILLED WITH NON-CONDUCTIVE EPOXY-RESIN AND PLATEOVER WITH COPPER." at 9024,564 h60
  text "Drill Table" at 3178.45,451.95 h60
  text "SURFACE MUST BE FLAT,FLATNESS TOLERANCE IS +0.000/-0.001\" ON TOP SIDE ONLY AND +0.000/-0.003 ON BOTTOM SIDE." at 9171.28,402.82 h60
  text "MINIMUM ANNULAR RING REQUIREMENT IS WAIVED FOR FILLED VIAS." at 9171.28,277.47 h60
  text "12. FOR 0.006\" VIA DRILL TOLERANCE SHOULD BE +0/-0.006\"." at 9024,114 h60
  text "13. 9.685 MIL DRILL TOLERANCE SHOULD BE +/-0.002\"." at 9035,-48 h60
  text "14. 9.685 MIL PTH HOLES NEED TO BE PLATED ON BOARD EDGE AT 22 PLACES." at 9039,-186 h60
  text "PROCESS NOTES:" at 8759,-593 h60
  text "P1. SOLDERMASK BOTH SIDES PER ARTWORK: GREEN  LPI" at 9009,-793 h60
  text "C" at 26990,-870.51 h200
  text "SOLDERMASK CLEARANCE IS GIVEN AS SAME AS PAD SIZE FOR ALL  SMT" at 9159,-993 h60
  text "FAB DRAWING" at -16.01,-1143.38 h75
  text "COMPONENT. VENDOR SHALL OVERSIZE THE MASK CLEARANCE" at 9159,-1193 h60
  text "13" at 320,-1262 h75
  text "AS PER THEIR MANUFACTURING CAPABILITIES" at 9159,-1393 h60
  text "P2. SILKSCREEN BOTH SIDES PER ARTWORK: COLOR=WHITE" at 9009,-1593 h60
  text "P3. PLATING:PLATE CIRCUITRY ON OUTER LAYERS TO 5-15 MICRO INCHES AU OVER MINIMUM OF 200 MICRO INCHES NI. KNOOP HARDNESS 130-200." at 9009,-1793 h60
  text "ALL UNITS ARE INCHES UNLESS OTHERWISE SPECIFIED." at -1262,-2495 h150
  text "DETAIL A" at 1627,-3152 h156
  text "SCALE:NONE" at 1519,-3487 h156
  text "LAYER STACKUP" at 1243,-3776 h156
  text "Cu" at 6344.01,-4066.07 h156
  text "P1" at 1648,-4172 h125
  text "P2" at 2048,-4172 h125
  text "P3" at 2448,-4172 h125
  text "MASK" at 4227,-4406 h100
  text "PLATING" at 4222,-4630 h100
  text "0.5OZ" at 6304,-4799 h100
  text "LAYER 1 TOP SIDE" at 4014,-4873.73 h100
  text "PREPREG" at 4014,-5067 h100
  text "LAYER 2 GND SPLIT PLANE 1" at 4014,-5275 h100
  text "0.5OZ" at 6312.01,-5280.1 h100
  text "PREPREG" at 4018,-5474.3 h100
  text "0.5OZ" at 6304,-5595 h100
  text "LAYER 3 SIGNAL 1" at 4018,-5682.3 h100
  text "5" at -694,-5781 h125
  text "PREPREG" at 4022,-5881.6 h100
  text "0.5OZ" at 6312.01,-6076.1 h100
  text "LAYER 4 SIGNAL 2" at 4022,-6089.6 h100
  text "PREPREG" at 4026,-6288.9 h100
  text "0.020\"(+/- 10%)" at -220,-6291 h100 r90
  text "B" at 27010,-6370.51 h200
  text "0.5OZ" at 6322,-6481 h100
  text "LAYER 5 POWER SPLIT PLANE 1" at 4026,-6496.9 h100
  text "PREPREG" at 4030,-6696.2 h100
  text "0.5OZ" at 6329,-6883 h100
  text "LAYER 6 BOTTOM SIDE" at 4030,-6904.2 h100
  text "PLATING" at 4270.8,-7173.8 h100
  text "MASK" at 4253.8,-7381.8 h100
  text "P1" at 1915,-7889 h125
  text "P2" at 2315,-7889 h125
  text "P3" at 2715,-7889 h125
  text "THIS IS A NON IMPEDANCE BOARD." at 645,-8489 h150
  text "MATERIAL:" at 21561.61,-10060.41 h75
  text "PROCESSES:" at 23270.6,-10060.09 h75
  text "SEE NOTES" at 21538.5,-10395 h75
  text "SEE" at 23388.5,-10395 h75
  text "NOTES" at 23388.5,-10545 h75
  text "NEXT ASSEMBLY" at 25443.28,-10726.38 h100
  text "SURFACE" at 26170.4,-10959.16 h75
  text "TOLERANCES UNLESS OTHERWISE SPECIFIED" at 22033.66,-11037.13 h100
  text "ROUGHNESS" at 26104.53,-11065.55 h75
  text "MISCELLANEOUS" at 24333.5,-11253 h100
  text "LINEAR" at 22308.5,-11258 h100
  text "o" at 24706.5,-11358 h57.09
  text "INCHES" at 22955.17,-11403.94 h100
  text "MILLIMETERS" at 21551.5,-11409 h100
  text "ANGLES +/- 1" at 23928.86,-11431.94 h75
  text "o" at 25408.5,-11503 h57.09
  text "o" at 25851.5,-11504 h57.09
  text ".XX  +/- .25" at 21524.5,-11558 h75
  text ".XXX +/- .010" at 22800.5,-11558 h75
  text "AXIS OF TAPPED HOLES 90  +/- 1" at 23978.86,-11581.94 h75
  text ".XX  +/- .020" at 22723.5,-11655 h75
  text ".X   +/- .50" at 21524.5,-11663 h75
  text "THIRD ANGLE" at 26030.59,-11672.91 h75
  text "REMOVE ALL BURRS & SHARP EDGES" at 23928.86,-11731.94 h75
  text "PROJECTION" at 26069.12,-11787.86 h75
  text "HOLES" at 22373.5,-11831 h100
  text "A" at 26990,-11870.51 h200
  text "MILLIMETERS" at 21501.5,-11983 h100
  text "INCHES" at 22902.17,-11989.94 h100
  text ".XXX +/- .076" at 21524.84,-12111.94 h75
  text ".XXX +/- .003" at 22674.84,-12111.94 h75
  text ".XX  +/- .127" at 21524.85,-12212.02 h75
  text ".XX  +/- .005" at 22674.85,-12212.02 h75
  text "CODE IDENTITY" at 26045.26,-12463.54 h75
  text "DATE:" at 22652.5,-12464 h100
  text "DRAFTSMAN:" at 21382.5,-12477 h100
  text "EXAS  NSTRUMENTS INC." at 23902.5,-12538 h100
  text "T" at 23762.91,-12540.17 h156
  text "I" at 24372.78,-12541.24 h156
  text "NUMBER" at 26192.5,-12566 h75
  text "11/25/13" at 22625.5,-12613 h75
  text "SIVAKUMAR" at 21367.41,-12620.02 h75
  text "SEMICONDUCTOR OPERATIONS" at 23974.73,-12695.03 h75
  text "01295" at 26119.63,-12728.7 h125
  text "DESIGNER:" at 21384.5,-12827 h100
  text "DATE:" at 22669.5,-12827 h100
  text "TITLE:" at 23270.67,-12911.82 h100
  text "FABRICATION" at 23988.5,-12945 h100
  text "SIVAKUMAR" at 21367.41,-12970.02 h75
  text "11/25/13" at 22642.5,-12976 h75
  text "DATE:" at 22663.5,-13169 h100
  text "CHECKER:" at 21377.5,-13171 h100
  text "QA TESSOLVE" at 21367.41,-13295.02 h75
  text "11/25/13" at 22636.5,-13318 h75
  text "DCM03_AFE4403_MCU" at 23462,-13349 h200
  text "DATE:" at 22672.5,-13473 h100
  text "ENGINEER:" at 21379.5,-13475 h100
  text "PRAVEEN" at 21367.41,-13595.02 h75
  text "11/25/13" at 22645.5,-13622 h75
  text "DATE:" at 22661.5,-13788 h100
  text "APPROVED:" at 21379.5,-13798 h100
  text "PRAVEEN" at 21367.41,-13920.02 h75
  text "11/25/13" at 22634.5,-13937 h75
  text "SCALE" at 23287.27,-14112.08 h75
  text "SHEET" at 26348.5,-14115 h75
  text "RELEASED:" at 21384.5,-14130 h100
  text "DATE:" at 22669.5,-14131 h100
  text "X0" at 25998.5,-14165 h125
  text "DCM03_AFE4403_MCU" at 24133,-14170 h100
  text "D" at 23778.5,-14185 h125
  text "1" at 26334.5,-14260 h125
  text "MIKE KORSON" at 21367.41,-14270.02 h75
  text "11/25/13" at 22642.5,-14280 h75
  text "N" at 23398.5,-14285 h125
  text "1" at 26638.5,-14285 h125
  text "SIZE" at 23717.16,-14298.33 h75
  text "REV" at 26004.24,-14298.33 h75
  text "WO#305848-5776-D" at 23762.5,-14580 h125

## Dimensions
487.26,-4360.25 to 485,-7340 on Drill Drawing
-59.05,-46.55 to 0,413.95 on M2 Board Dimensions
-59.05,-46.55 to 608.6,0.62 on M2 Board Dimensions
-12.4,413.95 to 0,0.62 on Drill Drawing
0,-0.05 to 608.6,-0.05 on Drill Drawing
